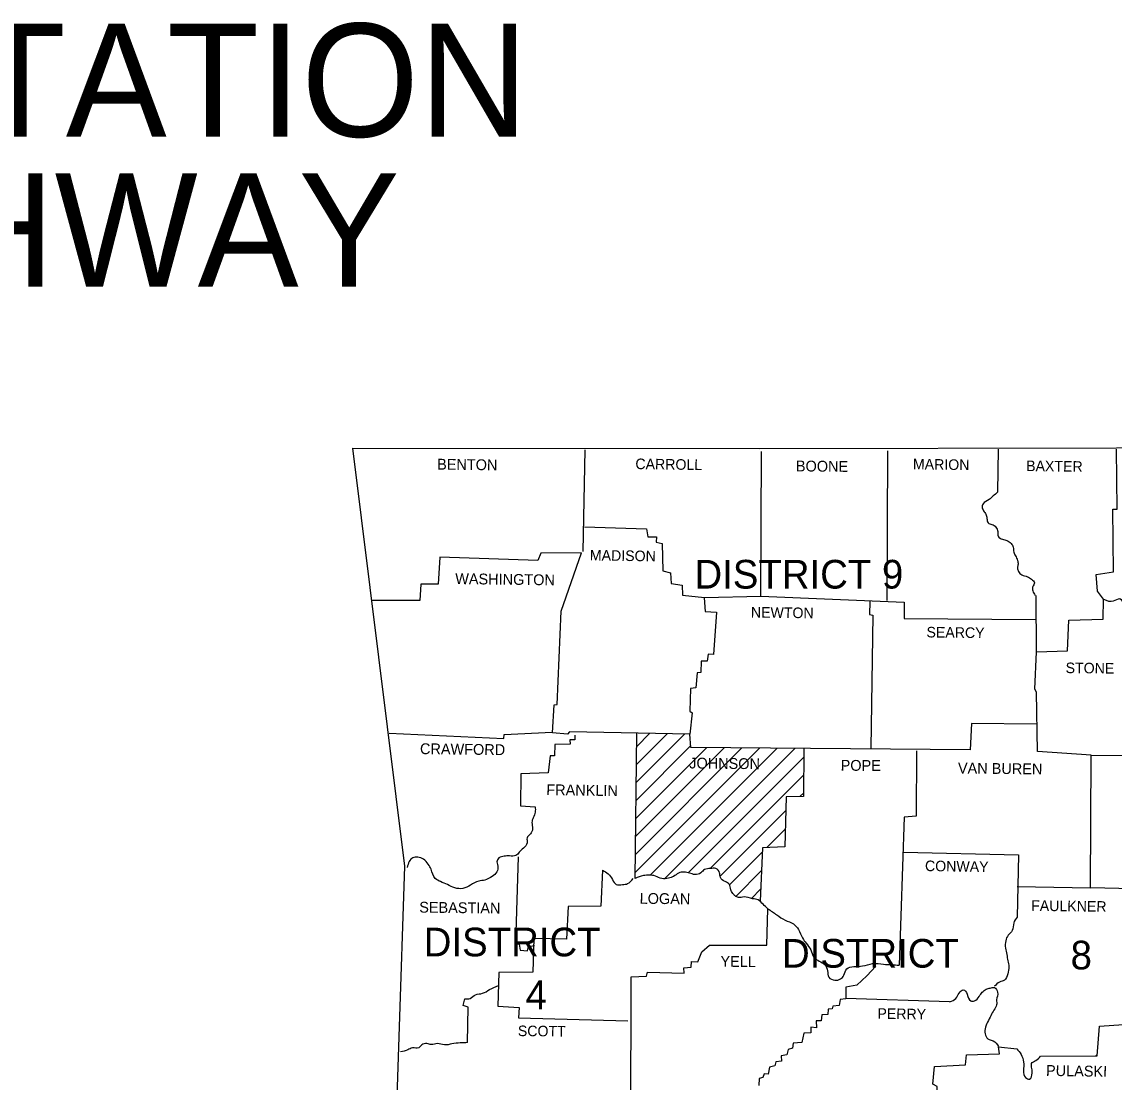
# Model space of a CAD drawing. Extents: x 1373884 to 1377798, y 1168424 to 1170626.
# Drawn here: x 1376164.1 to 1376598.2, y 1170029.4 to 1170450.9 of the extents above; entities that cross this region are included whole.
import ezdxf

# ---------------------------------------------------------------- set-up
doc = ezdxf.new("R2010")
doc.units = 0
doc.layers.add('2', color=7, linetype='Continuous')
doc.layers.add('R_Draft', color=7, linetype='Continuous')

msp = doc.modelspace()

# ---------------------------------------------------------------- linework, layer by layer
at = {"layer": 'R_Draft'}
for p, q in [((1376408.26, 1170148.55), (1376427.45, 1170167.74)), ((1376408.34, 1170155.71), (1376420.51, 1170167.87)), ((1376408.43, 1170162.87), (1376413.57, 1170168)), ((1376407.82, 1170112.76), (1376457.24, 1170162.18)), ((1376407.91, 1170119.92), (1376450.23, 1170162.24)), ((1376408, 1170127.08), (1376443.21, 1170162.3)), ((1376408.08, 1170134.24), (1376436.2, 1170162.35)), ((1376408.17, 1170141.39), (1376429.92, 1170163.15)), ((1376413.81, 1170111.68), (1376464.26, 1170162.13)), ((1376419.44, 1170110.24), (1376471.27, 1170162.07)), ((1376428.89, 1170112.62), (1376474.88, 1170158.6)), ((1376437.63, 1170114.29), (1376474.84, 1170151.5)), ((1376473.3, 1170142.88), (1376474.8, 1170144.39)), ((1376441.53, 1170111.12), (1376467.73, 1170137.31)), ((1376460.15, 1170122.66), (1376467.51, 1170130.02)), ((1376445.38, 1170107.89), (1376458.41, 1170120.93)), ((1376447.8, 1170103.24), (1376458.05, 1170113.49)), ((1376454.03, 1170102.4), (1376457.69, 1170106.06))]:
    msp.add_line(p, q, dxfattribs=at)
for points in [[(1376295.59, 1170281.4), (1376457.29, 1170281.3), (1376599.19, 1170281.6), (1376766.59, 1170284.2), (1376844.19, 1170286)], [(1376307.29, 1169843.9), (1376316.29, 1170115.2), (1376295.59, 1170281.4)], [(1376387.89, 1170280.8), (1376386.99, 1170240.3)], [(1376387.69, 1170250.2), (1376412.29, 1170249.4), (1376412.89, 1170246.2), (1376416.29, 1170246.1), (1376416.19, 1170244.1), (1376418.59, 1170243.5), (1376418.79, 1170232.6), (1376421.89, 1170231.9), (1376422.09, 1170227.6), (1376426.49, 1170227), (1376426.69, 1170223), (1376435.39, 1170222.1), (1376457.79, 1170222.6), (1376457.99, 1170280.1)], [(1376508.09, 1170280.3), (1376507.79, 1170220.9)], [(1376552.09, 1170281), (1376551.89, 1170263.9)], [(1376568.89, 1170039.7), (1376591.39, 1170039.8), (1376592.39, 1170051.6), (1376605.79, 1170052.6), (1376605.79, 1170106.2), (1376588.79, 1170106.7), (1376589.09, 1170159.4), (1376567.69, 1170160.8), (1376567.39, 1170184.4), (1376566.69, 1170185.6), (1376567.29, 1170200.4), (1376579.69, 1170200.8), (1376580.19, 1170213), (1376593.79, 1170213.5), (1376593.99, 1170221.4), (1376591.59, 1170224.5), (1376590.99, 1170231.2), (1376597.99, 1170232.2), (1376597.69, 1170257.1), (1376599.39, 1170257.2), (1376599.19, 1170281)], [(1376429.99, 1170162.4), (1376429.49, 1170167.7), (1376381.79, 1170168.6), (1376380.89, 1170167.7), (1376374.99, 1170168.2), (1376375.59, 1170179.4), (1376376.79, 1170179.5), (1376378.39, 1170216.6), (1376386.49, 1170239.8), (1376370.39, 1170239.7), (1376369.19, 1170236.7), (1376330.19, 1170238.1), (1376329.59, 1170227.4), (1376322.69, 1170227.4), (1376322.19, 1170220.8), (1376303.49, 1170220.9)], [(1376435.19, 1170221.9), (1376435.59, 1170216.5), (1376440.19, 1170216.2), (1376438.99, 1170199.4), (1376436.89, 1170199.5), (1376436.49, 1170196.8), (1376434.09, 1170196.8), (1376433.99, 1170192.2), (1376432.49, 1170192.1), (1376431.99, 1170186.2), (1376429.79, 1170185.9), (1376429.49, 1170176.9), (1376430.49, 1170176.2), (1376429.49, 1170167.7)], [(1376457.79, 1170222.6), (1376514.79, 1170220.2), (1376514.69, 1170213.7), (1376566.99, 1170213.3)], [(1376567.29, 1170200.4), (1376567.19, 1170222.9)], [(1376501.09, 1170220.5), (1376500.99, 1170215.3), (1376502.29, 1170215), (1376501.49, 1170162.2)], [(1376567.29, 1170171.7), (1376541.49, 1170172), (1376540.99, 1170161.5), (1376429.99, 1170162.4)], [(1376310.09, 1170168.1), (1376355.59, 1170166), (1376355.79, 1170167.6), (1376374.79, 1170168.5)], [(1376383.79, 1170167.3), (1376383.79, 1170165.5), (1376381.89, 1170165.5), (1376381.99, 1170163.7), (1376375.89, 1170163.6), (1376375.79, 1170159.1), (1376374.09, 1170159.1), (1376373.19, 1170152.4), (1376362.39, 1170151.9), (1376362.29, 1170139.2), (1376368.09, 1170138.8)], [(1376407.79, 1170110.4), (1376408.49, 1170168.1)], [(1376474.9, 1170162.04), (1376474.79, 1170142.9), (1376467.89, 1170142.8), (1376467.29, 1170122.9), (1376458.49, 1170122.6), (1376457.46, 1170101.34)], [(1376519.69, 1170161.1), (1376519.49, 1170135.1), (1376514.69, 1170134.7), (1376512.79, 1170075.9)], [(1376589.09, 1170159.4), (1376640.49, 1170159.1), (1376644.89, 1170161.2), (1376644.59, 1170122.1), (1376641.59, 1170120.8), (1376638.89, 1170118.5), (1376637.99, 1170117.6), (1376637.89, 1170106.4), (1376605.19, 1170106.4)], [(1376361.29, 1170119), (1376360.29, 1170084.6), (1376361.79, 1170084.2), (1376362.09, 1170081.8), (1376365.09, 1170081.6), (1376365.39, 1170083.3), (1376367.79, 1170083.7)], [(1376514.49, 1170120.8), (1376560.19, 1170119.7), (1376559.59, 1170095)], [(1376394.89, 1170113.6), (1376394.19, 1170099.3), (1376381.19, 1170099.2), (1376380.49, 1170086.2), (1376367.59, 1170086.5), (1376367.19, 1170073.1), (1376353.69, 1170073), (1376353.29, 1170059.6), (1376361.79, 1170059.1), (1376361.49, 1170055), (1376404.89, 1170053.8)], [(1376559.69, 1170107.1), (1376588.79, 1170106.7)], [(1376406.09, 1170012.8), (1376406.29, 1170071.3), (1376412.29, 1170071.5), (1376412.79, 1170073.1), (1376427.29, 1170072.7), (1376427.19, 1170074.8), (1376430.09, 1170075.1), (1376430.19, 1170077.4), (1376432.69, 1170077.2), (1376434.39, 1170081.2), (1376437.39, 1170083.8), (1376460.19, 1170083.9), (1376460.59, 1170098.3)], [(1376503.49, 1170075.5), (1376499.89, 1170071.6), (1376495.99, 1170067.9), (1376491.49, 1170067.2), (1376491.49, 1170062.5), (1376489.29, 1170062.2), (1376488.89, 1170059.8), (1376486.39, 1170059.6), (1376486.19, 1170058.5), (1376484.49, 1170058.4), (1376484.39, 1170056.3), (1376481.99, 1170056.2), (1376481.79, 1170053.8), (1376479.79, 1170053.8), (1376479.89, 1170051), (1376477.69, 1170051.2), (1376477.59, 1170049), (1376474.89, 1170048.8), (1376474.09, 1170045.2), (1376470.69, 1170044.9), (1376470.39, 1170042.9), (1376468.59, 1170042.4), (1376468.09, 1170040.3), (1376465.79, 1170039.8), (1376465.99, 1170037.7), (1376463.69, 1170037.5), (1376463.29, 1170035.9), (1376461.19, 1170035.3), (1376460.69, 1170032.6), (1376459.09, 1170032.7), (1376458.59, 1170031.3), (1376457.09, 1170030.8), (1376456.99, 1170028.1)], [(1376341.19, 1170045.1), (1376341.49, 1170059.2), (1376339.49, 1170059.8), (1376340.09, 1170062.5)], [(1376532.79, 1170061.3), (1376491.59, 1170062.6)], [(1376527.89, 1170023.1), (1376527.89, 1170027.7), (1376526.09, 1170028.6), (1376526.79, 1170035.6), (1376539.09, 1170036.3), (1376539.49, 1170040.2), (1376552.59, 1170040.7), (1376552.29, 1170043.4), (1376559.49, 1170042.6)], [(1376590.89, 1170039.9), (1376591.39, 1170040.4)]]:
    msp.add_lwpolyline(points, dxfattribs=at)
for points in [[(1376551.89, 1170263.9), (1376550.09, 1170262.4), (1376548.49, 1170261), (1376546.09, 1170259.3), (1376545.79, 1170257.7), (1376546.59, 1170256.1), (1376547.39, 1170254.8), (1376547.69, 1170253), (1376548.39, 1170251.5), (1376550.09, 1170250.9), (1376551.49, 1170249.6), (1376551.99, 1170247.8), (1376552.19, 1170246.1), (1376553.79, 1170245.3), (1376555.59, 1170244.7), (1376557.29, 1170243.5), (1376558.09, 1170242), (1376558.29, 1170240.1), (1376558.99, 1170238.6), (1376559.79, 1170236.8), (1376559.99, 1170235.3), (1376559.79, 1170233.8), (1376560.19, 1170232.4), (1376561.49, 1170231), (1376563.79, 1170230.3), (1376565.39, 1170229.3), (1376566.49, 1170227.9), (1376565.79, 1170226.2), (1376565.89, 1170224.7), (1376566.79, 1170222.9)], [(1376593.99, 1170221.4), (1376597.99, 1170220.7), (1376600.39, 1170221.6), (1376602.09, 1170219), (1376602.99, 1170217), (1376604.49, 1170214.1), (1376606.89, 1170213.2), (1376608.69, 1170211.6), (1376608.69, 1170209.9), (1376607.09, 1170208.3), (1376605.89, 1170206.7), (1376606.29, 1170204.8), (1376606.69, 1170202.2), (1376606.69, 1170199.7), (1376606.09, 1170197.4), (1376605.59, 1170195.3), (1376606.09, 1170193.5), (1376607.99, 1170193.8), (1376609.99, 1170195.3), (1376612.09, 1170195.3), (1376614.09, 1170194.2), (1376616.19, 1170192.3), (1376618.29, 1170192.7), (1376619.99, 1170193.2), (1376622.39, 1170193.9), (1376624.09, 1170193), (1376625.59, 1170191.8), (1376627.39, 1170189.9), (1376629.09, 1170188.7), (1376631.29, 1170187.6), (1376633.99, 1170186.9), (1376636.49, 1170185.2), (1376636.89, 1170182.3), (1376636.79, 1170179.8), (1376636.59, 1170176.7), (1376636.39, 1170173.3), (1376636.69, 1170170), (1376637.79, 1170167.8), (1376639.19, 1170165.2), (1376639.59, 1170162.8), (1376639.49, 1170159)], [(1376368.09, 1170138.8), (1376368.09, 1170136.7), (1376367.29, 1170134.5), (1376366.79, 1170132.6), (1376367.09, 1170130.1), (1376366.19, 1170128.1), (1376364.89, 1170126.5), (1376364.89, 1170124.5), (1376363.39, 1170122.4), (1376361.79, 1170120.8), (1376360.39, 1170119.5), (1376357.89, 1170119.3), (1376355.79, 1170119.2), (1376353.69, 1170118.5), (1376352.89, 1170117), (1376353.29, 1170114.7), (1376352.49, 1170112.5), (1376350.39, 1170110.8), (1376348.09, 1170109.7), (1376345.69, 1170109.3), (1376342.39, 1170107.7), (1376339.39, 1170106.4), (1376336.19, 1170106.6), (1376333.19, 1170107.9), (1376330.49, 1170109.1), (1376328.39, 1170110.3), (1376326.69, 1170114), (1376325.59, 1170116), (1376323.69, 1170118), (1376321.39, 1170118.8), (1376319.49, 1170118.6), (1376317.19, 1170114.7)], [(1376394.89, 1170113.6), (1376397.09, 1170112.2), (1376398.79, 1170109.9), (1376400.29, 1170108), (1376402.79, 1170107.9), (1376404.79, 1170108.3), (1376407.09, 1170110.3)], [(1376460.59, 1170098.3), (1376458.69, 1170100.1), (1376456.69, 1170101.8), (1376454.49, 1170102.3), (1376451.09, 1170103), (1376448.89, 1170102.8), (1376447.59, 1170103.4), (1376446.69, 1170104.4), (1376445.79, 1170105.9), (1376445.29, 1170108), (1376443.59, 1170109.1), (1376441.69, 1170110.8), (1376441.39, 1170112.6), (1376439.89, 1170114.3), (1376437.79, 1170114.3), (1376435.39, 1170113.9), (1376433.99, 1170112.6), (1376431.59, 1170111.9), (1376429.39, 1170112.5), (1376427.29, 1170112.9), (1376425.09, 1170112.5), (1376423.09, 1170111.2), (1376421.09, 1170110.5), (1376418.39, 1170110.3), (1376415.89, 1170111.3), (1376413.49, 1170111.7), (1376411.09, 1170111.5), (1376407.79, 1170110.4)], [(1376460.59, 1170098.3), (1376464.09, 1170095.9), (1376467.39, 1170093.8), (1376470.79, 1170092.3), (1376472.69, 1170090.1), (1376474.39, 1170086.7), (1376475.79, 1170084.6), (1376477.59, 1170082), (1376478.89, 1170079.1), (1376480.99, 1170077.5), (1376483.19, 1170076.1), (1376484.29, 1170073.6), (1376484.79, 1170071.1), (1376487.19, 1170069.9), (1376489.49, 1170070.4), (1376490.79, 1170071.9), (1376491.99, 1170074.5), (1376494.69, 1170075.3), (1376498.19, 1170075.6), (1376502.19, 1170076.5), (1376506.59, 1170076.3), (1376512.79, 1170075.9)], [(1376559.59, 1170095), (1376558.29, 1170092.7), (1376557.69, 1170089.7), (1376556.09, 1170087.8), (1376555.09, 1170085.6), (1376554.99, 1170082.7), (1376555.49, 1170080.1), (1376555.99, 1170077.6), (1376556.39, 1170075.3), (1376555.89, 1170072.4), (1376554.59, 1170069.9), (1376552.59, 1170069.2), (1376550.69, 1170067.5)], [(1376340.09, 1170062.5), (1376342.29, 1170062.7), (1376344.39, 1170064.1), (1376347.19, 1170064.7), (1376349.99, 1170066.2), (1376353.49, 1170067.8)], [(1376532.79, 1170061.3), (1376535.29, 1170062.7), (1376536.59, 1170064.8), (1376538.19, 1170066.1), (1376539.79, 1170064.3), (1376541.19, 1170061.7), (1376542.69, 1170061.7), (1376544.59, 1170063.5), (1376545.79, 1170065.1), (1376547.29, 1170066.3), (1376548.89, 1170066.8), (1376550.59, 1170067), (1376551.89, 1170065.1), (1376551.49, 1170062.1), (1376551.49, 1170060.1), (1376550.39, 1170058), (1376549.19, 1170055.8), (1376547.89, 1170053.3), (1376546.89, 1170050.6), (1376547.09, 1170048), (1376548.49, 1170046.3), (1376550.09, 1170045.8), (1376552.29, 1170043.6)], [(1376341.19, 1170045.1), (1376338.29, 1170045), (1376334.99, 1170044.6), (1376331.99, 1170044.2), (1376329.29, 1170044.7), (1376326.79, 1170044.3), (1376325.09, 1170044.7), (1376322.99, 1170044.2), (1376321.79, 1170043), (1376319.29, 1170043), (1376317.49, 1170042.2), (1376314.59, 1170041.5)], [(1376559.49, 1170042.6), (1376561.19, 1170040.4), (1376562.19, 1170037.4), (1376562.19, 1170034), (1376562.99, 1170031.2), (1376564.59, 1170030.6), (1376565.59, 1170033), (1376565.39, 1170035.4), (1376565.39, 1170036.8), (1376567.09, 1170038), (1376568.89, 1170039.7)]]:
    msp.add_spline(points, degree=3, dxfattribs=at)

# ---------------------------------------------------------------- texts
at = {"layer": '2'}
for s, p in [('ARKANSAS DEPARTMENT OF TRANSPORTATION', (1374934.42, 1170405.21)), ('CONSTRUCTION PLANS FOR STATE HIGHWAY', (1374956.84, 1170345.61))]:
    msp.add_text(s, height=45, dxfattribs=at).set_placement(p)
at = {"layer": 'R_Draft'}
for s, height, rotation, p in [('BENTON', 4.301, 359.2527, (1376329.09, 1170272.9)), ('CARROLL', 4.201, 359.1481, (1376407.89, 1170273.1)), ('BOONE', 4.301, 359.4001, (1376471.69, 1170272.2)), ('MARION', 4.201, 359.1854, (1376518.19, 1170273)), ('BAXTER', 4.201, 359.2559, (1376563.19, 1170272.3)), ('MADISON', 4.201, 359.0906, (1376389.79, 1170236.8)), ('WASHINGTON', 4.3, 359.232, (1376336.29, 1170227.4)), ('NEWTON', 4.201, 359.2717, (1376453.79, 1170214.1)), ('SEARCY', 4.199, 359.2527, (1376523.59, 1170206.2)), ('STONE', 4.199, 359.4001, (1376578.89, 1170192)), ('CRAWFORD', 4.3, 359.2771, (1376322.29, 1170159.8)), ('JOHNSON', 4.301, 359.3514, (1376429.29, 1170154.1)), ('POPE', 4.301, 359.6155, (1376489.49, 1170153.2)), ('VAN BUREN', 4.301, 359.3508, (1376536.09, 1170152.1)), ('FRANKLIN', 4.301, 359.1815, (1376372.49, 1170143.5)), ('CONWAY', 4.199, 359.0371, (1376522.99, 1170113.3)), ('LOGAN', 4.301, 359.3969, (1376409.59, 1170100.3)), ('SEBASTIAN', 4.3, 359.2816, (1376321.99, 1170096.8)), ('FAULKNER', 4.201, 359.2486, (1376565.19, 1170097.5)), ('YELL', 4.301, 359.1987, (1376441.69, 1170075.3)), ('PERRY', 4.201, 359.0858, (1376504.09, 1170054.6)), ('SCOTT', 4.201, 359.4063, (1376361.19, 1170047.7)), ('PULASKI', 4.301, 359.053, (1376571.09, 1170031.9))]:
    msp.add_text(s, height=height, rotation=rotation, dxfattribs=at).set_placement(p)
for s, p in [('DISTRICT 9', (1376431.39, 1170225.6)), ('DISTRICT', (1376323.79, 1170079.4)), ('DISTRICT', (1376466.19, 1170074.9)), ('8', (1376580.89, 1170074.2)), ('4', (1376364.29, 1170058.4))]:
    msp.add_text(s, height=11.4, dxfattribs=at).set_placement(p)

doc.saveas('drawing.dxf')
